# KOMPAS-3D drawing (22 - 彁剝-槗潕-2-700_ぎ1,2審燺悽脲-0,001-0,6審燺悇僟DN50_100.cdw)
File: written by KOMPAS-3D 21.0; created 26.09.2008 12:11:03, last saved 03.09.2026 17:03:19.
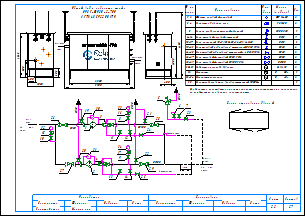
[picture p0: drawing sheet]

Sheets 1-2: A3, landscape

Document properties: Наименование: Макро:21; Автор: RaskoAdmin; Форматы листов документа: 2xA3; Полное имя файла: \\UR38nt01\Departments\КТО\КБ ПУРДГ\Заявки\Прайс-лист на типовые шкафы ГРПШ\ПРДГ_стандарт_20_03_2026\ПРДГ с РДГ(Н, В)\ПРДГ-ШУЭО-2-700_до1,2МПа_Рвых-0,001-0,6МПа_РДГ_DN50_100.cdw

Title block, sheet 1: Наименование: Пункт учета газа / ПУГ-Ш-400-Р / ЛГТИ.485922.001ТУ; designation: ЛГТИ.03.4411141; sheet number: 1; Количество листов документа: 2; organisation: ООО "ЭЛЬСТЕР Газэлектроника"; Форматы листов документа: A3; stored path: C:\Рабочие документы\Компас\ПУГ\Схема.cdw; Разработал: Устинов; Проверил: Кошкин; Утвердил: Кошкин
Title block, sheet 2: sheet number: 2; stored path: D:\Рабочие документы\Заявки\ПУРДГ\ПУРДГ-ШУЭО-2-100-Р 4411220.cdw; designation, second copy: ЛГТИ.03.4411141-

Views: Вид 1, Вид 2
Referenced files: wcvoit.frw
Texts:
  Normal
  № на
  схеме
  Усл.
  обозн.
  Марка
  (модель)
  Кол.
  Фильтр газовый фланцевый
  ФГ 16-50
  Регулятор давления газа
  РДГ-50
  Клапан предохранительный сбросной
  КПС DN20
  Кран шаровой газовый латунный
  DN15
  Кран кнопочный VE-РАСКО-НЗ-1,6-G1/2-М20
  Кран шаровой "под приварку" штуцерный DN20 PN16
  Кран шаровой "под приварку" штуцерный п/п DN20 PN16
  DN20
  Кран шаровой фланцевый DN50 PN16
  Кран шаровой фланцевый DN100 PN16
  DN50
  DN100
  Индикатор перепада давления
  Delta 15
  Манометр
  Манометр-напоромер
  Электрообогреватель взрывозащищенный 1000Вт
  0...     МПа
  0...     кПа
  Общий вид и габариты шкафа
  ПРДГ-ШУЭО-2-700
  Выход газа
  Вход газа
  logo-rasko-ge.png
  Вход
  газа
  PDI
  Выход
  Р=     кПа
  Импульс DN20
  ≥5DN
  HYSWLongFangSong
  Р=       МПа
  Схема открывания дверей
  Предприятие изготовитель может заменять комплектующие на аналогичные,
  не ухудшающие заявленных характеристик.
  Должность
  Конструктор
  Фамилия
  Подпись
  Дата
  Согласовано
  Максимкин
  Лист
  Листов
  POLYLINE_STYLE_0.18_RGB_0_0_0
  POLYLINE_STYLE_0.50_RGB_0_0_0
  POLYLINE_STYLE_0.34_RGB_0_0_0
  PHANTOM_RGB_0_0_0_SC_1_THICK_0.18
  K5LT_THIN_RGB_0_0_0_THICK_0.18
  K5LT32769_RGB_0_0_0_THICK_0.18
  K5LT12_RGB_0_0_0_SC_1_THICK_0.18
  K5LT_DASHED_RGB_0_0_0_SC_1_THICK_0.18
  ACISOTGL_RGB_0_0_0_SC_0.8_THICK_0.25
  CONTINUOUS_RGB_0_127_31_THICK_0.3
  CONTINUOUS_RGB_0_0_255_THICK_0.35
  CONTINUOUS_RGB_255_0_0_THICK_0.35
  POLYLINE_STYLE_0.25_RGB_0_0_0
  CONTINUOUS_RGB_0_0_0_THICK_0.5
  POLYLINE_STYLE_0.35_RGB_0_0_255
  CONTINUOUS_RGB_0_0_0_THICK_0.4
  CONTINUOUS_RGB_0_0_0_THICK_0.35
  Без оформления
Dimensions and other numbers on the sheet: 1; 1, 2; 2; 3, 4; 5; 6-14; 9; 15-17; 3; 18-23; 24-25; 6; 26-27; 28-29; 30-31; 32; 33-34; 35; 400; 1050; 500; 305; 1565; 3100; 1000; 4130; 2800; 4; 10; 27; 28; 29; 23; 8; 12; 19; 20; 21; 22; 25; 24; 30; 31; 15; 16; 26; 7; 11; 14; 13; 33; 17; 34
